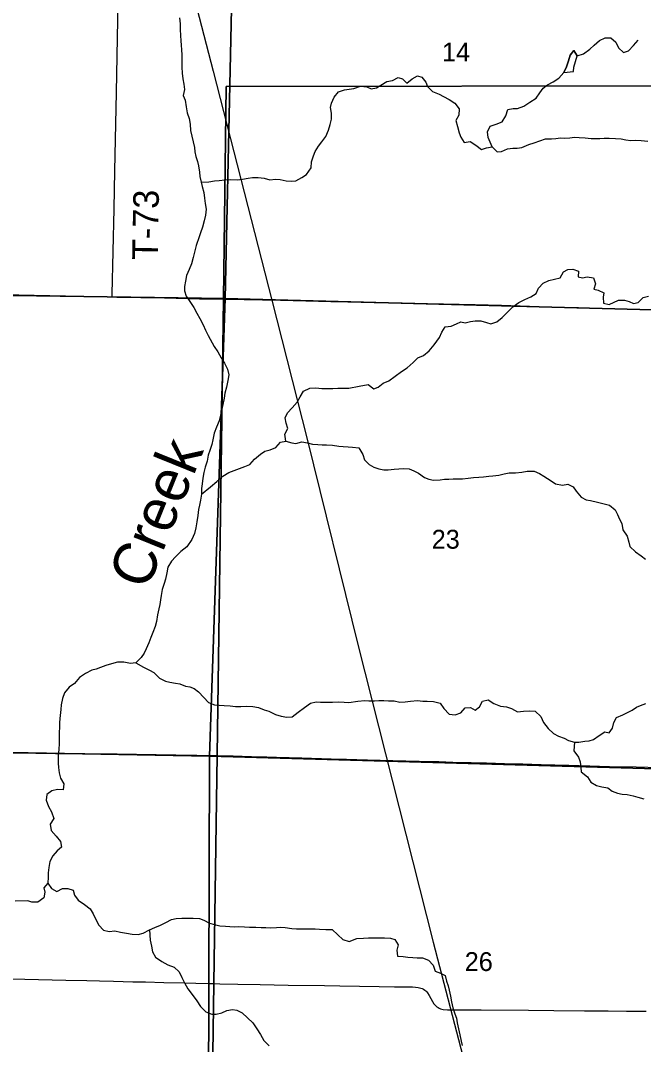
# Model space of a CAD drawing. Extents: x 0 to 34, y 0 to 22.
# Drawn here: x 6.585 to 7.968, y 17.017 to 19.29 of the extents above; entities that cross this region are included whole.
import ezdxf

# ---------------------------------------------------------------- set-up
doc = ezdxf.new("R2010")
doc.units = 0
for name, color, linetype in [('Default', 7, 'Continuous'), ('GM_X_City_Street', 7, 'Continuous'), ('GM_X_Corporation', 7, 'Continuous'), ('GM_X_County_Road_Text', 7, 'Continuous'), ('GM_X_Interchange_Ramps', 7, 'Continuous'), ('GM_X_Major_River', 7, 'Continuous'), ('GM_X_Major_River_Text', 7, 'Continuous'), ('GM_X_Minor_River', 7, 'Continuous'), ('GM_X_Section', 7, 'Continuous'), ('GM_X_Unincorporated_Location', 7, 'Continuous')]:
    doc.layers.add(name, color=color, linetype=linetype)

msp = doc.modelspace()

# ---------------------------------------------------------------- linework, layer by layer
at = {"layer": 'Default'}
for points in [[(7.0025, 16.32), (7.0145, 17.1525), (7.0215, 17.6587), (7.0359, 18.6717), (7.042, 19.1437), (8.0868, 19.1446), (8.0872, 19.1572), (8.0903, 19.2721), (8.0916, 19.3249)], [(8.8, 14), (8.8, 18.8069), (8.0776, 18.8052), (8.0812, 18.9398), (8.0831, 19.0143), (8.0851, 19.0888), (8.0868, 19.1446), (7.042, 19.1437), (7.0359, 18.6717), (7.0215, 17.6587), (7.0145, 17.1525), (7.0025, 16.32)]]:
    msp.add_lwpolyline(points, dxfattribs=at)
at = {"layer": 'GM_X_City_Street'}
for points in [[(6.2929, 18.6864), (6.5133, 18.6821), (6.6158, 18.6801), (6.7887, 18.6761)], [(6.7887, 18.6761), (6.799, 18.6759), (6.9046, 18.674), (6.9823, 18.6722), (7.0361, 18.6712)], [(7.0361, 18.6712), (7.0817, 18.6703), (7.1624, 18.6687), (7.2183, 18.6674), (7.2742, 18.6663), (7.3115, 18.6656), (7.3705, 18.6642), (7.4326, 18.6629), (7.4885, 18.6619), (7.5941, 18.6594), (7.6531, 18.6577), (7.7773, 18.6538), (7.8239, 18.6526), (7.9854, 18.6475), (8.0568, 18.6446), (8.0661, 18.644), (8.0736, 18.6435)], [(6.2774, 17.6702), (6.2811, 17.67), (6.3246, 17.6691), (6.4146, 17.6672), (6.4674, 17.6663), (6.5078, 17.6653), (6.5637, 17.6644), (6.6196, 17.6635), (6.6627, 17.663)], [(6.6627, 17.663), (6.6817, 17.6628), (6.7283, 17.6624), (6.7998, 17.6617), (6.8867, 17.6607), (6.9302, 17.6599), (6.9767, 17.6588), (7.0171, 17.6582), (7.0218, 17.6581)], [(7.0218, 17.6581), (7.0575, 17.6573), (7.0978, 17.6562), (7.132, 17.6553), (7.1537, 17.6545), (7.2096, 17.6531), (7.2748, 17.6511), (7.309, 17.6501), (7.3555, 17.6488), (7.4114, 17.6475), (7.4704, 17.6459), (7.5139, 17.6447), (7.5449, 17.6438), (7.5853, 17.6427), (7.6194, 17.6417), (7.6598, 17.6403), (7.7002, 17.6395), (7.7405, 17.6383), (7.8026, 17.6367), (7.8492, 17.6355), (7.8927, 17.6342), (7.9517, 17.633), (8.0045, 17.6318)], [(6.5648, 17.1625), (6.6859, 17.1597), (6.7324, 17.1586), (6.7604, 17.1579), (6.7914, 17.157), (6.8348, 17.1562), (6.8628, 17.1556), (6.9031, 17.1547), (6.9497, 17.1536), (6.9745, 17.1529), (7.0024, 17.1521), (7.0147, 17.1519)], [(7.0147, 17.1519), (7.0273, 17.1517), (7.0676, 17.1509), (7.1173, 17.1498), (7.1794, 17.1487), (7.2601, 17.1474), (7.2942, 17.1468), (7.3377, 17.1464), (7.3811, 17.1453), (7.4153, 17.145), (7.4556, 17.1445), (7.4618, 17.1442), (7.468, 17.1434), (7.471, 17.1428), (7.474, 17.1419), (7.4769, 17.1408), (7.4797, 17.1394), (7.4823, 17.1377), (7.4847, 17.1358), (7.4868, 17.1336), (7.4887, 17.1311), (7.492, 17.1258), (7.4993, 17.1121), (7.5028, 17.107), (7.5048, 17.1046), (7.5069, 17.1023), (7.5093, 17.1004), (7.5119, 17.0986), (7.5146, 17.0972), (7.5175, 17.096), (7.5205, 17.0952), (7.5235, 17.0947), (7.5328, 17.094), (7.5453, 17.0939), (7.5701, 17.0938), (7.6074, 17.0934), (7.7129, 17.0928), (7.7688, 17.0925), (7.8371, 17.0918), (7.8899, 17.0913), (7.9302, 17.0909), (7.9737, 17.0906)]]:
    msp.add_lwpolyline(points, dxfattribs=at)
at = {"layer": 'GM_X_Corporation'}
msp.add_lwpolyline([(6.5927, 20.8), (6.6173, 20.7022), (6.732, 20.2629), (6.8332, 19.8757), (6.9052, 19.5948), (7.0125, 19.1776), (7.1431, 18.6694), (7.2218, 18.3603), (7.335, 17.9018), (7.5012, 17.2442), (7.5672, 16.9911), (7.6376, 16.714), (7.7025, 16.4605), (7.7388, 16.3223), (7.7626, 16.2427), (7.7756, 16.2117), (7.8081, 16.1506), (7.8441, 16.0969), (7.8846, 16.0477), (7.9314, 15.9998), (7.9673, 15.9687)], dxfattribs=at)
at = {"layer": 'GM_X_Interchange_Ramps'}
msp.add_lwpolyline([(6.7887, 18.6761), (6.7888, 18.6826), (6.7928, 18.872), (6.7948, 18.9558), (6.7982, 19.1297), (6.801, 19.2911), (6.8063, 19.5209), (6.8072, 19.5737), (6.8083, 19.6234), (6.8088, 19.6637), (6.8087, 19.6824), (6.8087, 19.6918)], dxfattribs=at)
at = {"layer": 'GM_X_Major_River'}
for points in [[(7.8208, 19.2112), (7.8136, 19.223), (7.8052, 19.2127), (7.8018, 19.2002), (7.7972, 19.1869), (7.7911, 19.1744)], [(7.7911, 19.1744), (7.8128, 19.1766), (7.8132, 19.1861), (7.8208, 19.2112)]]:
    msp.add_lwpolyline(points, dxfattribs=at)
at = {"layer": 'GM_X_Section'}
for points in [[(6.938, 19.2954), (6.9395, 19.2825), (6.9399, 19.27), (6.9407, 19.2567), (6.9412, 19.2446), (6.9416, 19.2351), (6.9424, 19.2249), (6.9435, 19.2135), (6.9436, 19.1998), (6.9433, 19.1862), (6.9441, 19.1733), (6.9456, 19.1604), (6.9476, 19.1483), (6.9495, 19.1365), (6.9465, 19.1236), (6.9504, 19.113), (6.9531, 19.0982), (6.9554, 19.085), (6.9596, 19.0725), (6.9619, 19.06), (6.9627, 19.0455), (6.9654, 19.0334), (6.9681, 19.0205), (6.9712, 19.0076), (6.972, 18.9982), (6.9747, 18.9883), (6.9778, 18.9769), (6.9805, 18.9675), (6.9824, 18.9535), (6.9836, 18.9436), (6.9863, 18.9311), (6.9882, 18.9216), (6.992, 18.908), (6.9936, 18.8958), (6.9952, 18.8833), (6.9971, 18.8708), (6.996, 18.8575), (6.9926, 18.845), (6.9893, 18.831), (6.9848, 18.8188), (6.9821, 18.8093), (6.9754, 18.7903), (6.9713, 18.7759), (6.9686, 18.7638), (6.9645, 18.7497), (6.9596, 18.7372), (6.954, 18.7235), (6.9514, 18.7114), (6.9495, 18.6992), (6.9496, 18.6898), (6.953, 18.6776), (6.961, 18.6659), (6.9702, 18.653), (6.9767, 18.6405), (6.9832, 18.6284), (6.9904, 18.614), (6.9958, 18.6027), (7.0015, 18.5906), (7.0152, 18.5663)], [(7.632, 19.0091), (7.6233, 19.03), (7.6218, 19.043), (7.6279, 19.0555), (7.6412, 19.0597), (7.6545, 19.065), (7.6621, 19.0783), (7.6671, 19.092), (7.6788, 19.0946), (7.6884, 19.0942), (7.7024, 19.0995), (7.7158, 19.1083), (7.7295, 19.1174), (7.7382, 19.1295), (7.7454, 19.1398), (7.755, 19.147), (7.7675, 19.1535), (7.7801, 19.1618), (7.7911, 19.1744), (7.7972, 19.1869), (7.8018, 19.2002), (7.8052, 19.2127), (7.8136, 19.223), (7.8208, 19.2112), (7.8345, 19.2161), (7.8486, 19.226), (7.8588, 19.2351), (7.8703, 19.2454), (7.8828, 19.2511), (7.8954, 19.2511), (7.9068, 19.2416), (7.9125, 19.229), (7.9235, 19.2188), (7.9349, 19.2226), (7.946, 19.2343), (7.9559, 19.2461)], [(7.3395, 19.1443), (7.3536, 19.1426), (7.3635, 19.1384), (7.3753, 19.1403), (7.3848, 19.146), (7.3981, 19.1544), (7.4111, 19.157), (7.4236, 19.1635), (7.4331, 19.16), (7.443, 19.1505), (7.4548, 19.16), (7.4666, 19.1669), (7.4761, 19.1642), (7.4849, 19.1532), (7.4887, 19.1437), (7.4997, 19.1323), (7.5141, 19.1266), (7.5244, 19.1213), (7.5366, 19.1144), (7.5491, 19.1061), (7.5586, 19.0935), (7.5583, 19.0798), (7.5518, 19.0677), (7.5552, 19.0544), (7.5586, 19.0407), (7.5624, 19.0308), (7.57, 19.019), (7.5833, 19.0209), (7.5959, 19.013), (7.6084, 19.0038), (7.6198, 19.0072), (7.632, 19.0091), (7.6434, 18.9985), (7.6529, 18.9993), (7.6659, 19.005), (7.6777, 19.0068), (7.6876, 19.0061), (7.6978, 19.0076), (7.7138, 19.0144), (7.7256, 19.0186), (7.7382, 19.0224), (7.7503, 19.027), (7.7636, 19.027), (7.7735, 19.0277), (7.7838, 19.0296), (7.7937, 19.0288), (7.8047, 19.0296), (7.8146, 19.0307), (7.8249, 19.03), (7.8382, 19.0296), (7.8515, 19.0281), (7.8614, 19.0277), (7.8713, 19.0281), (7.8808, 19.0284), (7.8918, 19.0288), (7.9055, 19.0277), (7.9185, 19.0269), (7.9287, 19.025), (7.9398, 19.0238), (7.9504, 19.0242), (7.963, 19.0238), (7.9778, 19.0219)], [(6.9863, 18.9311), (7.003, 18.9319), (7.0158, 18.9338), (7.0261, 18.9346), (7.039, 18.9358), (7.0519, 18.9366), (7.0659, 18.9363), (7.0777, 18.9378), (7.0906, 18.9398), (7.1, 18.9413), (7.1129, 18.941), (7.1258, 18.9395), (7.1384, 18.9365), (7.1513, 18.9373), (7.1619, 18.937), (7.1752, 18.934), (7.1858, 18.9329), (7.196, 18.9337), (7.21, 18.9417), (7.2203, 18.9478), (7.2301, 18.9626), (7.2312, 18.9759), (7.2353, 18.9896), (7.239, 18.999), (7.2466, 19.0112), (7.2538, 19.0207), (7.2628, 19.0325), (7.2685, 19.0462), (7.2722, 19.0591), (7.2756, 19.0705), (7.2752, 19.0841), (7.2736, 19.0966), (7.2758, 19.1065), (7.2811, 19.1194), (7.2913, 19.1316), (7.3046, 19.1362), (7.3148, 19.1377), (7.325, 19.1389), (7.3395, 19.1443)], [(7.3367, 18.4782), (7.3571, 18.4819), (7.3693, 18.472), (7.3788, 18.4758), (7.3898, 18.4846), (7.4024, 18.4899), (7.4168, 18.5001), (7.4309, 18.5104), (7.4435, 18.5191), (7.4564, 18.5309), (7.4674, 18.5408), (7.48, 18.5464), (7.4926, 18.5567), (7.5036, 18.57), (7.5154, 18.5859), (7.5204, 18.5981), (7.528, 18.6095), (7.5413, 18.611), (7.5527, 18.6167), (7.5626, 18.6213), (7.5721, 18.6186), (7.5839, 18.6216), (7.5942, 18.6235), (7.6071, 18.6231), (7.6196, 18.6193), (7.6292, 18.6163), (7.6421, 18.6209), (7.6546, 18.6307), (7.6661, 18.6425), (7.6779, 18.6539), (7.6916, 18.6641), (7.7049, 18.6706), (7.7182, 18.6763), (7.7296, 18.6835), (7.7346, 18.696), (7.7452, 18.7067), (7.7582, 18.7128), (7.7707, 18.7154), (7.7829, 18.7188), (7.7901, 18.7317), (7.8, 18.7374), (7.811, 18.7378), (7.824, 18.7332), (7.8232, 18.7211), (7.8327, 18.7188), (7.843, 18.7211), (7.8571, 18.7184), (7.8616, 18.7055), (7.8578, 18.6937), (7.8673, 18.6914), (7.8799, 18.685), (7.8783, 18.6755), (7.8791, 18.6622), (7.892, 18.6595), (7.9126, 18.6694), (7.9259, 18.669), (7.9362, 18.666), (7.946, 18.6614), (7.9563, 18.6637), (7.967, 18.6751), (7.9791, 18.6777)], [(7.0152, 18.5663), (7.0229, 18.5546), (7.0305, 18.541), (7.0378, 18.5289), (7.045, 18.5156), (7.0477, 18.5035), (7.0451, 18.491), (7.0425, 18.4758), (7.0391, 18.4625), (7.0369, 18.4515), (7.0343, 18.4378), (7.032, 18.4272), (7.0291, 18.4135), (7.0261, 18.4014), (7.02, 18.3873), (7.0152, 18.3741), (7.0122, 18.3593), (7.0096, 18.3486), (7.0051, 18.3353), (7.0021, 18.3251), (6.9994, 18.3118), (6.9949, 18.2985), (6.992, 18.2864), (6.9901, 18.2742), (6.9882, 18.2613), (6.9871, 18.2511), (6.9868, 18.2382), (6.9846, 18.2253), (6.9823, 18.2143), (6.9805, 18.2044), (6.979, 18.1908), (6.9768, 18.1771), (6.9742, 18.1634), (6.9712, 18.1509), (6.9652, 18.1376), (6.9542, 18.1216), (6.941, 18.111), (6.9293, 18.0996), (6.9202, 18.0893), (6.9123, 18.0764), (6.91, 18.0639), (6.9074, 18.0498), (6.9041, 18.0403), (6.8999, 18.027), (6.8973, 18.0134), (6.8958, 18.0039), (6.8944, 17.9933), (6.8925, 17.9838), (6.8895, 17.9709), (6.8869, 17.9561), (6.8839, 17.9443), (6.879, 17.9314), (6.8745, 17.9204), (6.87, 17.9082), (6.864, 17.8949), (6.8595, 17.8854), (6.8527, 17.8759), (6.8409, 17.8638), (6.8292, 17.8626), (6.8148, 17.8652), (6.8007, 17.8651), (6.7875, 17.8621), (6.775, 17.8582), (6.7625, 17.8533), (6.753, 17.8502), (6.7435, 17.8479), (6.7295, 17.8403), (6.7163, 17.8315), (6.7053, 17.8182), (6.6932, 17.8098), (6.683, 17.7972), (6.6781, 17.7851), (6.6755, 17.7711), (6.6744, 17.7604), (6.6722, 17.7407), (6.6719, 17.7305), (6.6715, 17.721), (6.6712, 17.7092), (6.6712, 17.6956), (6.6709, 17.6853), (6.6702, 17.6709), (6.6691, 17.6603), (6.6691, 17.6409), (6.6696, 17.6315), (6.6711, 17.6201), (6.6742, 17.6083), (6.6811, 17.5951), (6.6796, 17.5822), (6.6674, 17.5829), (6.6549, 17.5802), (6.6436, 17.5715), (6.6425, 17.5589), (6.6475, 17.5453), (6.6543, 17.5332), (6.659, 17.5188), (6.6514, 17.5055), (6.6534, 17.4918), (6.6644, 17.4794), (6.6743, 17.4676), (6.6766, 17.4548), (6.6664, 17.4468)], [(7.1745, 18.356), (7.1718, 18.3719), (7.1786, 18.3841), (7.1752, 18.3958), (7.1725, 18.4076), (7.1777, 18.4193), (7.1879, 18.4304), (7.1993, 18.4425), (7.2057, 18.4547), (7.2136, 18.4672), (7.2276, 18.4737), (7.2409, 18.4745), (7.2538, 18.4731), (7.2678, 18.4727), (7.2781, 18.4731), (7.2898, 18.4736), (7.3042, 18.474), (7.3141, 18.474), (7.3367, 18.4782)], [(6.9868, 18.2382), (7.0072, 18.2546), (7.0212, 18.2664), (7.0345, 18.2782), (7.0473, 18.2866), (7.0591, 18.2911), (7.0712, 18.2954), (7.0829, 18.2996), (7.0939, 18.3042), (7.1049, 18.3163), (7.1177, 18.3274), (7.1276, 18.3338), (7.1397, 18.3369), (7.1522, 18.3423), (7.1624, 18.3537), (7.1745, 18.356), (7.1871, 18.3522), (7.1966, 18.3511), (7.2098, 18.3542), (7.2223, 18.3524), (7.2334, 18.3494), (7.2451, 18.3483), (7.2546, 18.3479), (7.2645, 18.3476), (7.2774, 18.3469), (7.2918, 18.345), (7.3017, 18.3443), (7.3123, 18.3432), (7.3218, 18.3428), (7.3361, 18.3409)], [(7.3361, 18.3409), (7.3452, 18.3261), (7.349, 18.3144), (7.3593, 18.3041), (7.3696, 18.298), (7.3802, 18.2946), (7.3916, 18.2923), (7.4015, 18.2927), (7.4144, 18.2942), (7.4251, 18.295), (7.4346, 18.2957), (7.4479, 18.295), (7.4582, 18.2904), (7.4685, 18.2851), (7.4821, 18.2752), (7.4917, 18.2714), (7.5019, 18.2695), (7.5168, 18.2702), (7.5263, 18.2714), (7.5362, 18.2717), (7.5457, 18.2725), (7.5556, 18.2721), (7.5662, 18.2725), (7.5788, 18.274), (7.5906, 18.2751), (7.6027, 18.2763), (7.6126, 18.277), (7.6244, 18.2782), (7.6339, 18.2789), (7.6469, 18.2808), (7.659, 18.2835), (7.6701, 18.2858), (7.6841, 18.2861), (7.6978, 18.2876), (7.71, 18.2892), (7.7256, 18.2895), (7.7374, 18.2846), (7.7469, 18.2781), (7.7629, 18.2679), (7.7728, 18.2614), (7.788, 18.2584), (7.7998, 18.2603), (7.8119, 18.2545), (7.8188, 18.245), (7.8294, 18.2314), (7.8405, 18.226), (7.8503, 18.2245), (7.8659, 18.2203), (7.8804, 18.2169), (7.8922, 18.2139), (7.9051, 18.2036), (7.9101, 18.193), (7.915, 18.1827), (7.9196, 18.1732), (7.9222, 18.1591), (7.9317, 18.1455), (7.9351, 18.1322), (7.9374, 18.1219), (7.9503, 18.1101), (7.9629, 18.1014), (7.9724, 18.0938)], [(6.8409, 17.8638), (6.8584, 17.8547), (6.8714, 17.8479), (6.8809, 17.8427), (6.8938, 17.8302), (6.9071, 17.823), (6.9166, 17.8208), (6.9295, 17.8185), (6.939, 17.8174), (6.9515, 17.8125), (6.961, 17.8107), (6.9709, 17.8073), (6.9804, 17.7997), (6.9918, 17.7869), (7.0025, 17.7763), (7.0158, 17.7707), (7.026, 17.7699), (7.0374, 17.7692), (7.0503, 17.7689), (7.0624, 17.7674), (7.0742, 17.7671), (7.0863, 17.7675), (7.1007, 17.7668), (7.1133, 17.7645), (7.1262, 17.76), (7.1364, 17.757), (7.1513, 17.7495), (7.1638, 17.7454), (7.1763, 17.7431), (7.1885, 17.7443), (7.2013, 17.7542), (7.2153, 17.7649), (7.2286, 17.7744), (7.2418, 17.7771), (7.2513, 17.7764), (7.2634, 17.7768), (7.2779, 17.7768), (7.2908, 17.7776), (7.3037, 17.7765), (7.3139, 17.7762), (7.3338, 17.7787)], [(7.3338, 17.7787), (7.3491, 17.7802), (7.3587, 17.7798), (7.3708, 17.7798), (7.3803, 17.7802), (7.3917, 17.7802), (7.402, 17.7794), (7.4149, 17.7798), (7.4275, 17.7767), (7.4389, 17.7771), (7.4511, 17.779), (7.4663, 17.7802), (7.4781, 17.779), (7.488, 17.7786), (7.5017, 17.7779), (7.5165, 17.7741), (7.5249, 17.7627), (7.5363, 17.7501), (7.5496, 17.7482), (7.5629, 17.7528), (7.5724, 17.7638), (7.5842, 17.7649), (7.5941, 17.7592), (7.6036, 17.766), (7.6109, 17.779), (7.623, 17.782), (7.636, 17.774), (7.6508, 17.7679), (7.6641, 17.766), (7.6748, 17.7626), (7.6881, 17.755), (7.7018, 17.7569), (7.7151, 17.7576), (7.7272, 17.7565), (7.7398, 17.7451), (7.7463, 17.7318), (7.7561, 17.7181), (7.7683, 17.7071), (7.779, 17.7014), (7.7919, 17.6968), (7.8018, 17.6915), (7.8151, 17.6881), (7.8246, 17.6877), (7.8379, 17.69), (7.8474, 17.6911), (7.8569, 17.6941), (7.8699, 17.7029), (7.8824, 17.7105), (7.8919, 17.7086), (7.8992, 17.7192), (7.9018, 17.7314), (7.9083, 17.7424), (7.9224, 17.7488), (7.9327, 17.7538), (7.9425, 17.7591), (7.9521, 17.7659), (7.9616, 17.769), (7.9734, 17.7739)], [(7.8151, 17.6881), (7.8132, 17.6683), (7.8238, 17.6546), (7.8276, 17.644), (7.8287, 17.6315), (7.8299, 17.622), (7.844, 17.6113), (7.8508, 17.5988), (7.8637, 17.5916), (7.8755, 17.5885), (7.8888, 17.5862), (7.8987, 17.5794), (7.9105, 17.5744), (7.9204, 17.5722), (7.9318, 17.5718), (7.9451, 17.5687), (7.9554, 17.5657), (7.9687, 17.5623)], [(6.6664, 17.4468), (6.657, 17.4357), (6.6506, 17.4228), (6.648, 17.4099), (6.6469, 17.3978), (6.6469, 17.3883), (6.6462, 17.375), (6.6367, 17.3644), (6.639, 17.3549), (6.6368, 17.3427), (6.6236, 17.3328), (6.6107, 17.3328), (6.6012, 17.3354), (6.5735, 17.3353)], [(6.6462, 17.375), (6.6542, 17.3633), (6.6656, 17.3565), (6.6788, 17.363), (6.6906, 17.3634), (6.7024, 17.3596), (6.7051, 17.3479), (6.7131, 17.3373), (6.7271, 17.3279), (6.7401, 17.318), (6.7466, 17.3067), (6.7523, 17.2946), (6.7588, 17.2817), (6.7691, 17.2707), (6.782, 17.2674), (6.7945, 17.2693), (6.807, 17.2663), (6.8207, 17.2637), (6.8328, 17.2618), (6.8465, 17.2608), (6.8575, 17.2642), (6.8719, 17.2715), (6.8832, 17.2768), (6.8957, 17.2818), (6.9078, 17.2879), (6.9207, 17.294), (6.931, 17.2963), (6.9431, 17.2975), (6.9564, 17.2975), (6.9685, 17.2972), (6.9822, 17.2965), (6.992, 17.2931), (7.005, 17.2859), (7.0156, 17.2829), (7.0274, 17.2799), (7.0399, 17.2796), (7.0497, 17.2785), (7.0596, 17.2781), (7.0691, 17.2786), (7.0827, 17.2778), (7.0938, 17.2771), (7.1074, 17.2772), (7.1195, 17.2768), (7.1298, 17.2765), (7.1393, 17.2761), (7.1533, 17.2766), (7.1632, 17.277), (7.1727, 17.2762), (7.1871, 17.2744), (7.1977, 17.2737), (7.2121, 17.2733), (7.2243, 17.2738), (7.239, 17.2738), (7.2489, 17.2727), (7.2629, 17.2724), (7.277, 17.2717), (7.2895, 17.2599), (7.3006, 17.2497), (7.3146, 17.2456), (7.3316, 17.252)], [(6.8719, 17.2715), (6.8731, 17.2483), (6.8758, 17.2354), (6.8781, 17.2226), (6.885, 17.2108), (6.8987, 17.201), (6.9123, 17.1938), (6.9264, 17.1886), (6.9371, 17.178), (6.9432, 17.1655), (6.9489, 17.1534), (6.9565, 17.1405), (6.9661, 17.1276), (6.9764, 17.114), (6.9844, 17.1012), (6.9965, 17.0894), (7.0102, 17.0838), (7.0197, 17.0842), (7.0318, 17.0873), (7.0432, 17.0923), (7.0561, 17.0946), (7.0656, 17.0927), (7.0774, 17.0874), (7.0892, 17.0761), (7.1009, 17.0651), (7.1101, 17.0519), (7.1181, 17.0386), (7.1254, 17.0258), (7.1372, 17.0137)], [(7.3316, 17.252), (7.3462, 17.2529), (7.3573, 17.2532), (7.393, 17.2532), (7.4063, 17.2525), (7.4158, 17.2498), (7.4231, 17.238), (7.4204, 17.2259), (7.4223, 17.2129), (7.4345, 17.2122), (7.4447, 17.2106), (7.4558, 17.2099), (7.4653, 17.2091), (7.4778, 17.2091), (7.4911, 17.2038), (7.5014, 17.1928), (7.5052, 17.1799), (7.5177, 17.1753), (7.5276, 17.1696), (7.531, 17.1574), (7.5345, 17.1472), (7.5367, 17.1377), (7.5398, 17.1244), (7.5421, 17.1118), (7.5451, 17.0985), (7.5489, 17.0849), (7.5527, 17.0754), (7.5546, 17.0651), (7.5576, 17.0518), (7.5603, 17.0385), (7.5633, 17.0244), (7.5656, 17.0142)]]:
    msp.add_lwpolyline(points, dxfattribs=at)
at = {"layer": 'GM_X_Unincorporated_Location'}
for points in [[(6.0459, 19.7005), (7.0617, 19.6888), (7.0397, 18.6727), (6.0441, 18.6866)], [(7.0617, 19.6888), (8.0628, 19.6744), (8.0433, 18.6458), (7.0397, 18.6727)], [(6.0441, 18.6866), (7.0397, 18.6727), (7.0045, 17.6571), (6.0388, 17.6742)], [(7.0397, 18.6727), (8.0433, 18.6458), (8.0346, 17.8251), (8.0227, 17.628), (7.0045, 17.6571)], [(7.0045, 17.6571), (7.0019, 16.6421), (6.0154, 16.6684), (6.0388, 17.6742)], [(7.0045, 17.6571), (8.0227, 17.628), (8.0236, 17.3548), (8.0033, 16.6164), (7.0019, 16.6421)]]:
    msp.add_lwpolyline(points, close=True, dxfattribs=at)

# ---------------------------------------------------------------- texts
at = {"layer": 'GM_X_County_Road_Text'}
msp.add_text('T-73', height=0.05682, rotation=88.9457, dxfattribs=at).set_placement((6.8898, 18.7575))
at = {"layer": 'GM_X_Major_River_Text'}
for s, p in [('14', (7.5208, 19.1989)), ('23', (7.4979, 18.1174)), ('26', (7.5712, 17.1799))]:
    msp.add_text(s, height=0.04186, rotation=0, dxfattribs=at).set_placement(p)
at = {"layer": 'GM_X_Minor_River'}
msp.add_text('Creek', height=0.09471, rotation=67.973, dxfattribs=at).set_placement((6.866, 18.0227))

doc.saveas('drawing.dxf')
